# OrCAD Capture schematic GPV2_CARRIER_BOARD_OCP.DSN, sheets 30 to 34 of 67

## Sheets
30 035 M.2_G: size C
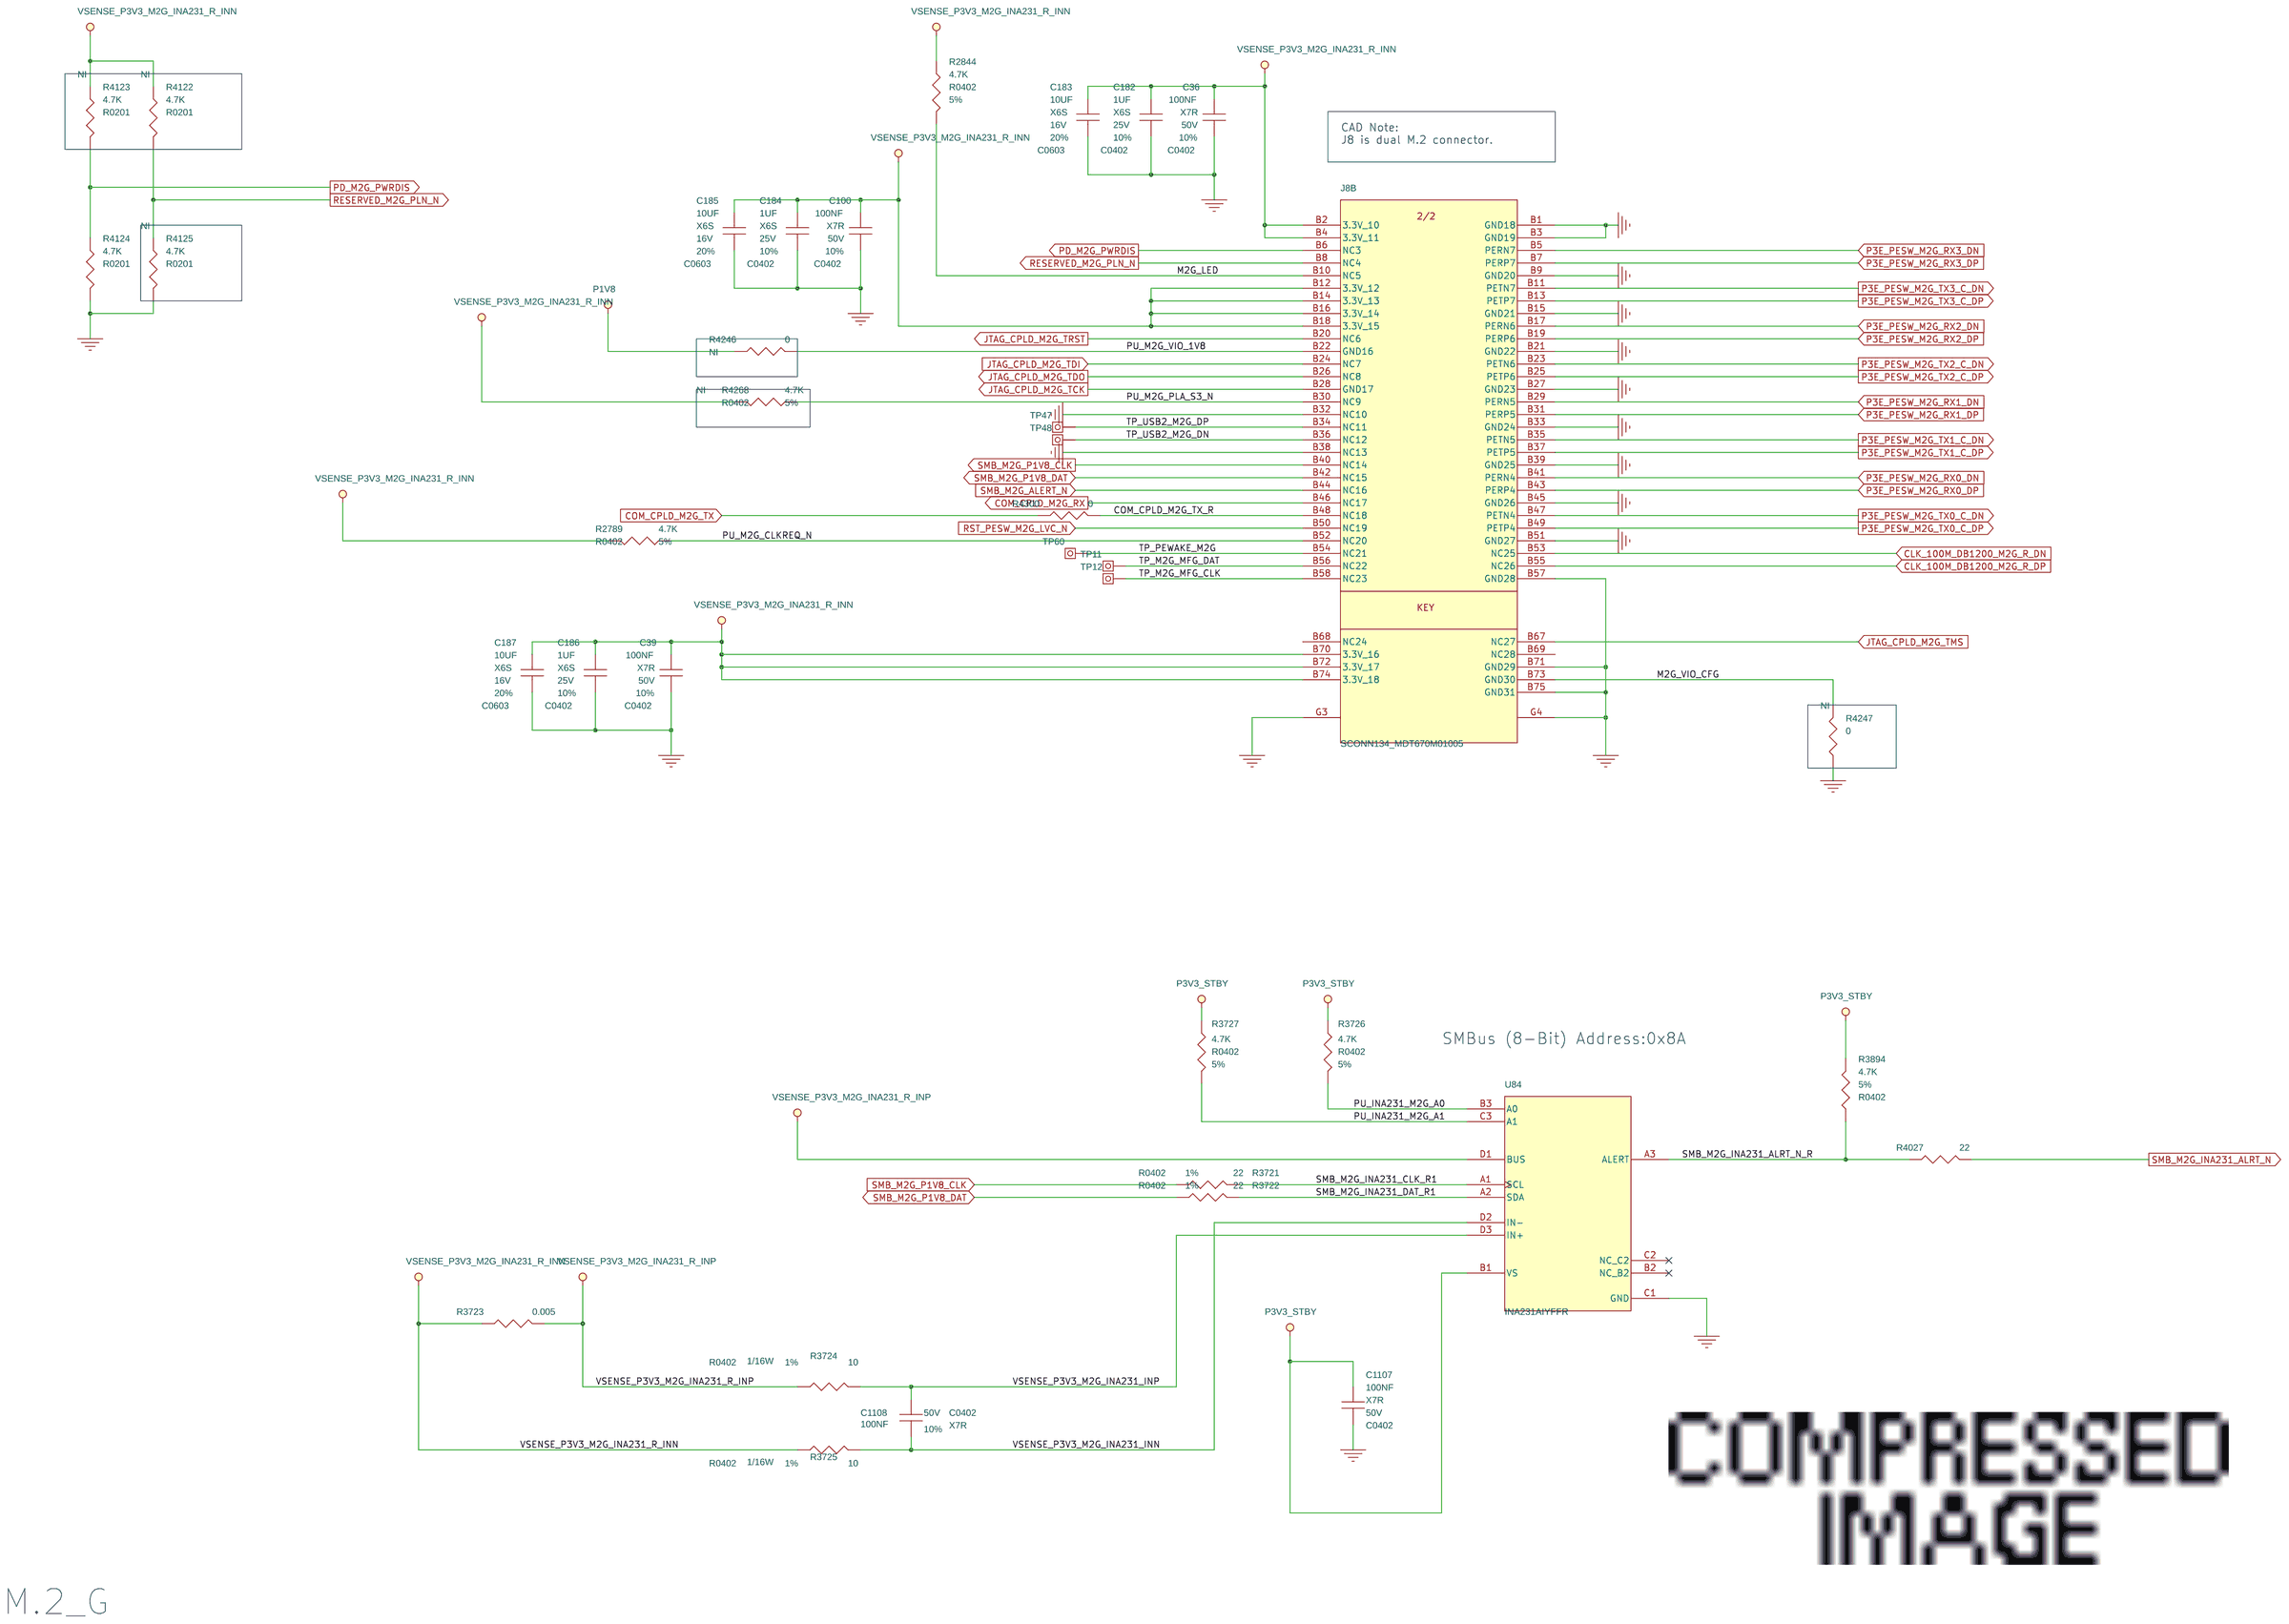
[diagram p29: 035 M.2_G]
31 036 M.2_H: size C
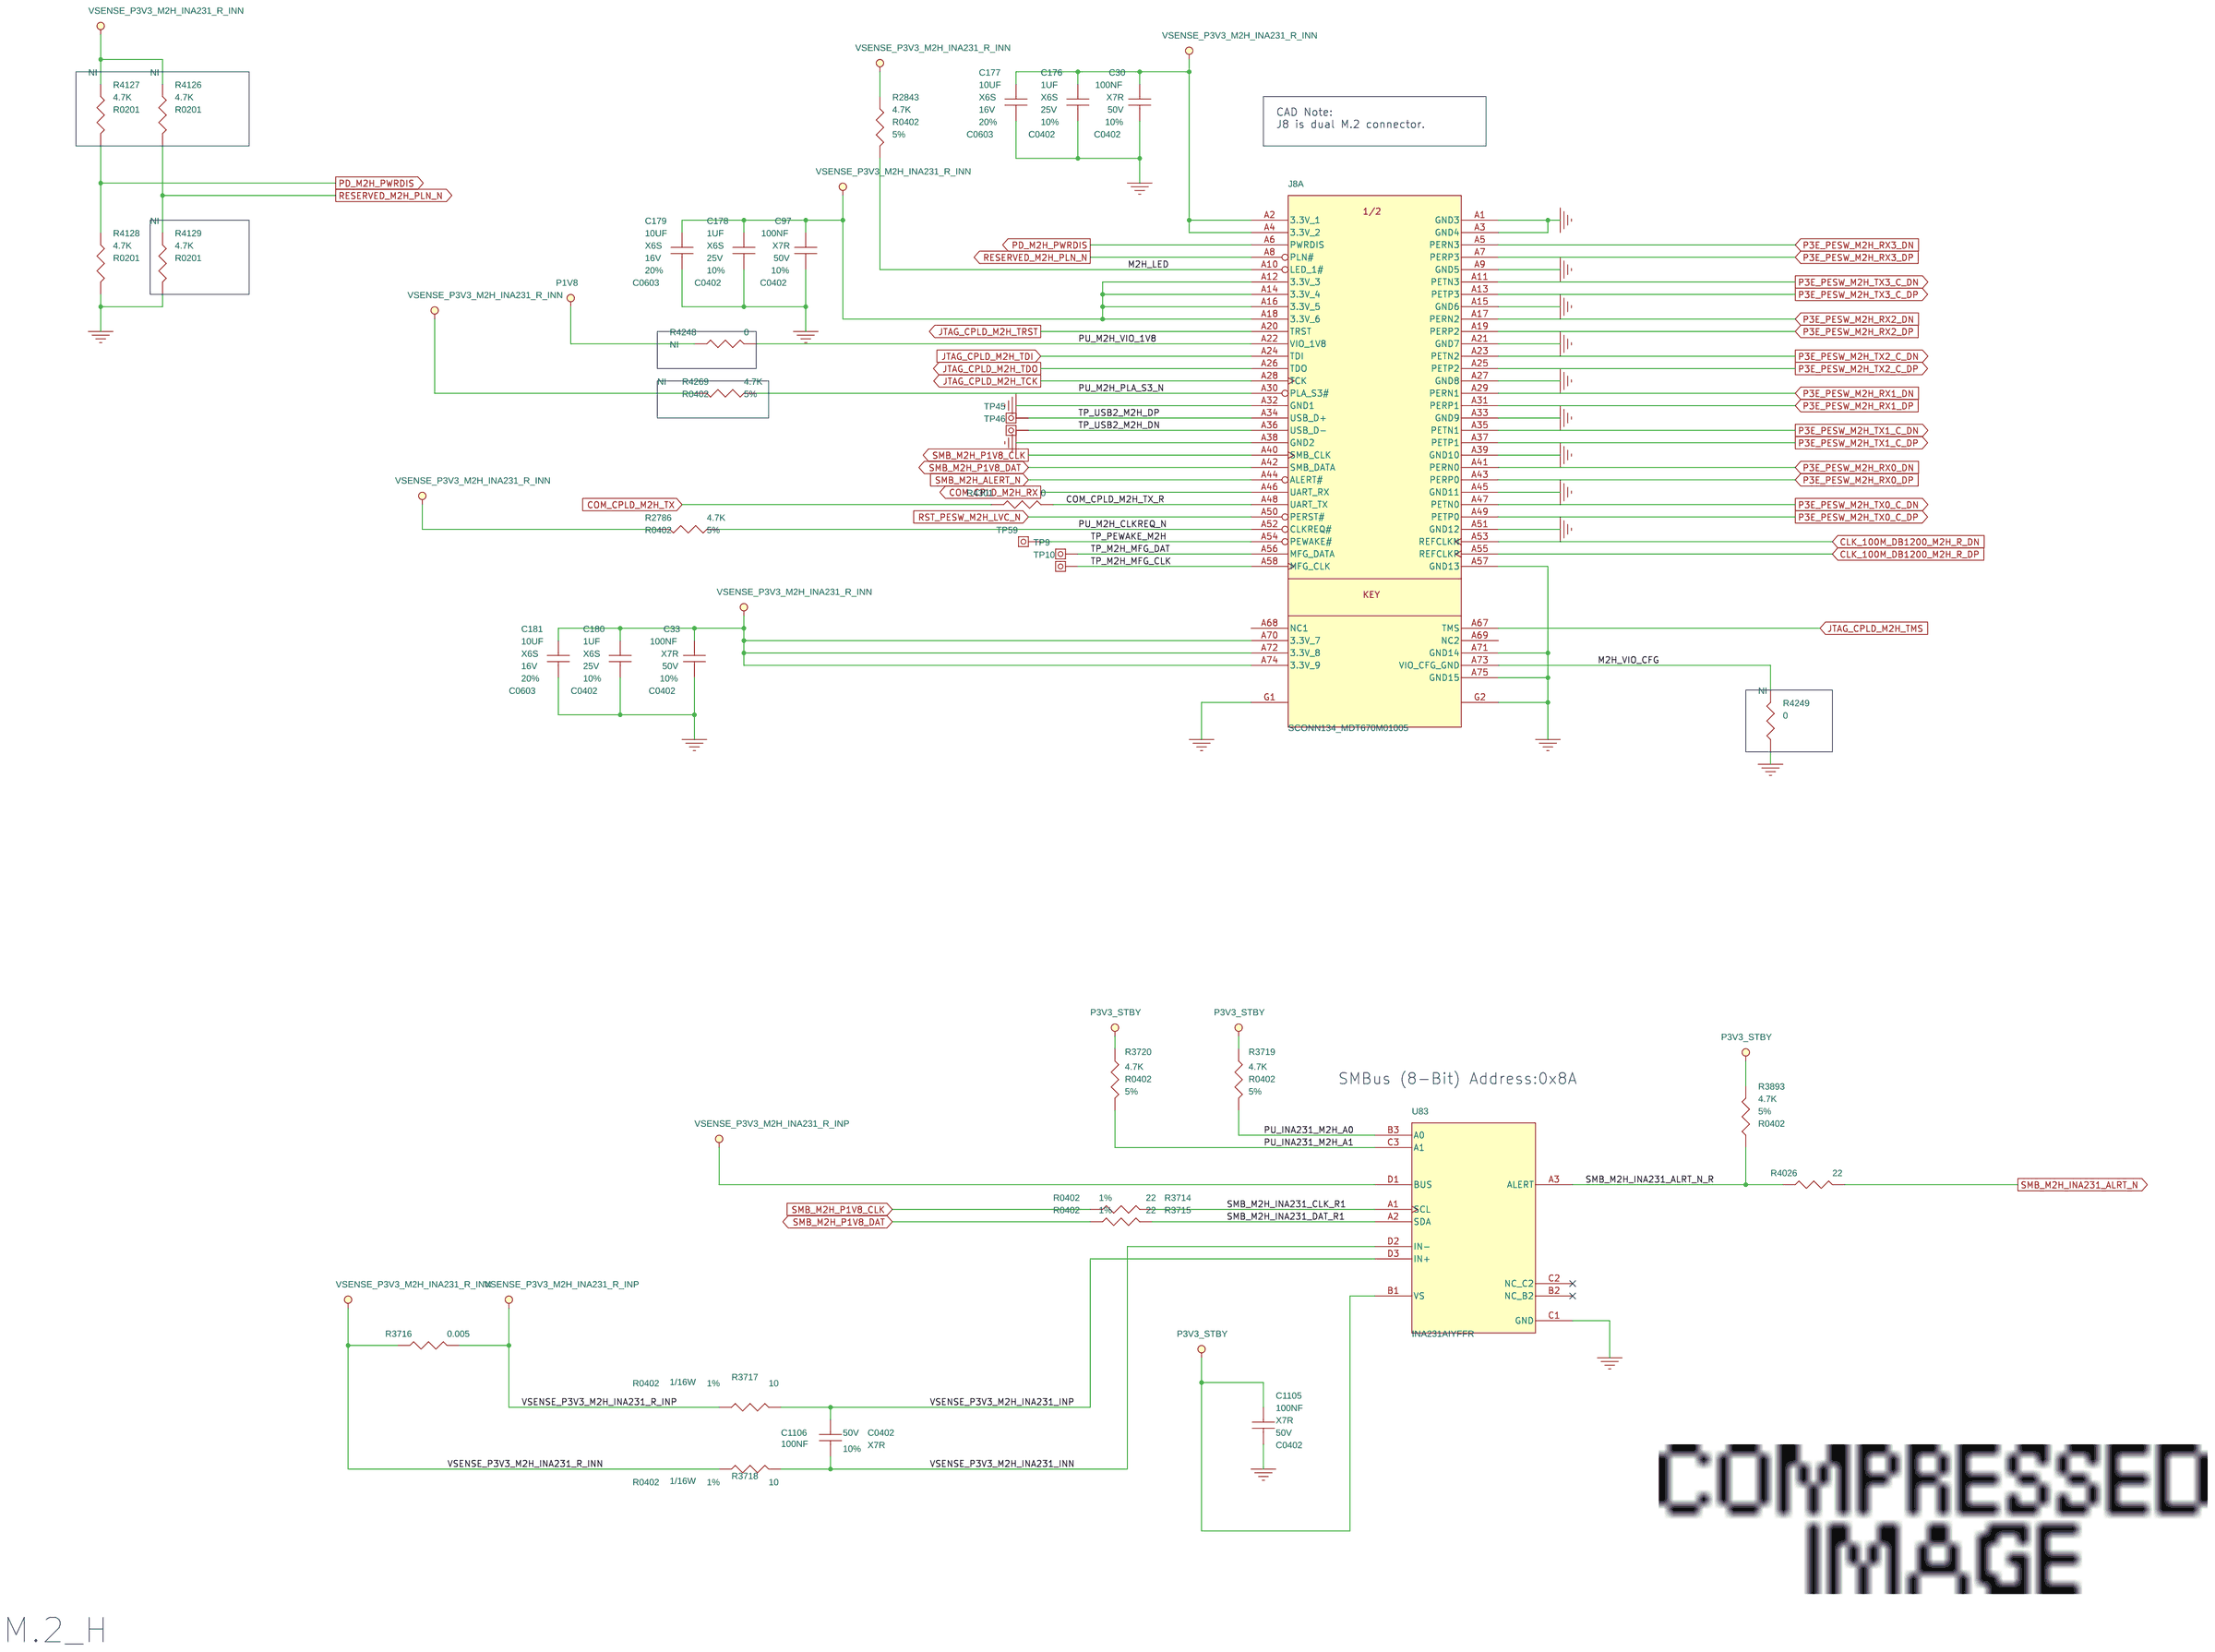
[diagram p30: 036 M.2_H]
32 037 M.2_I: size C
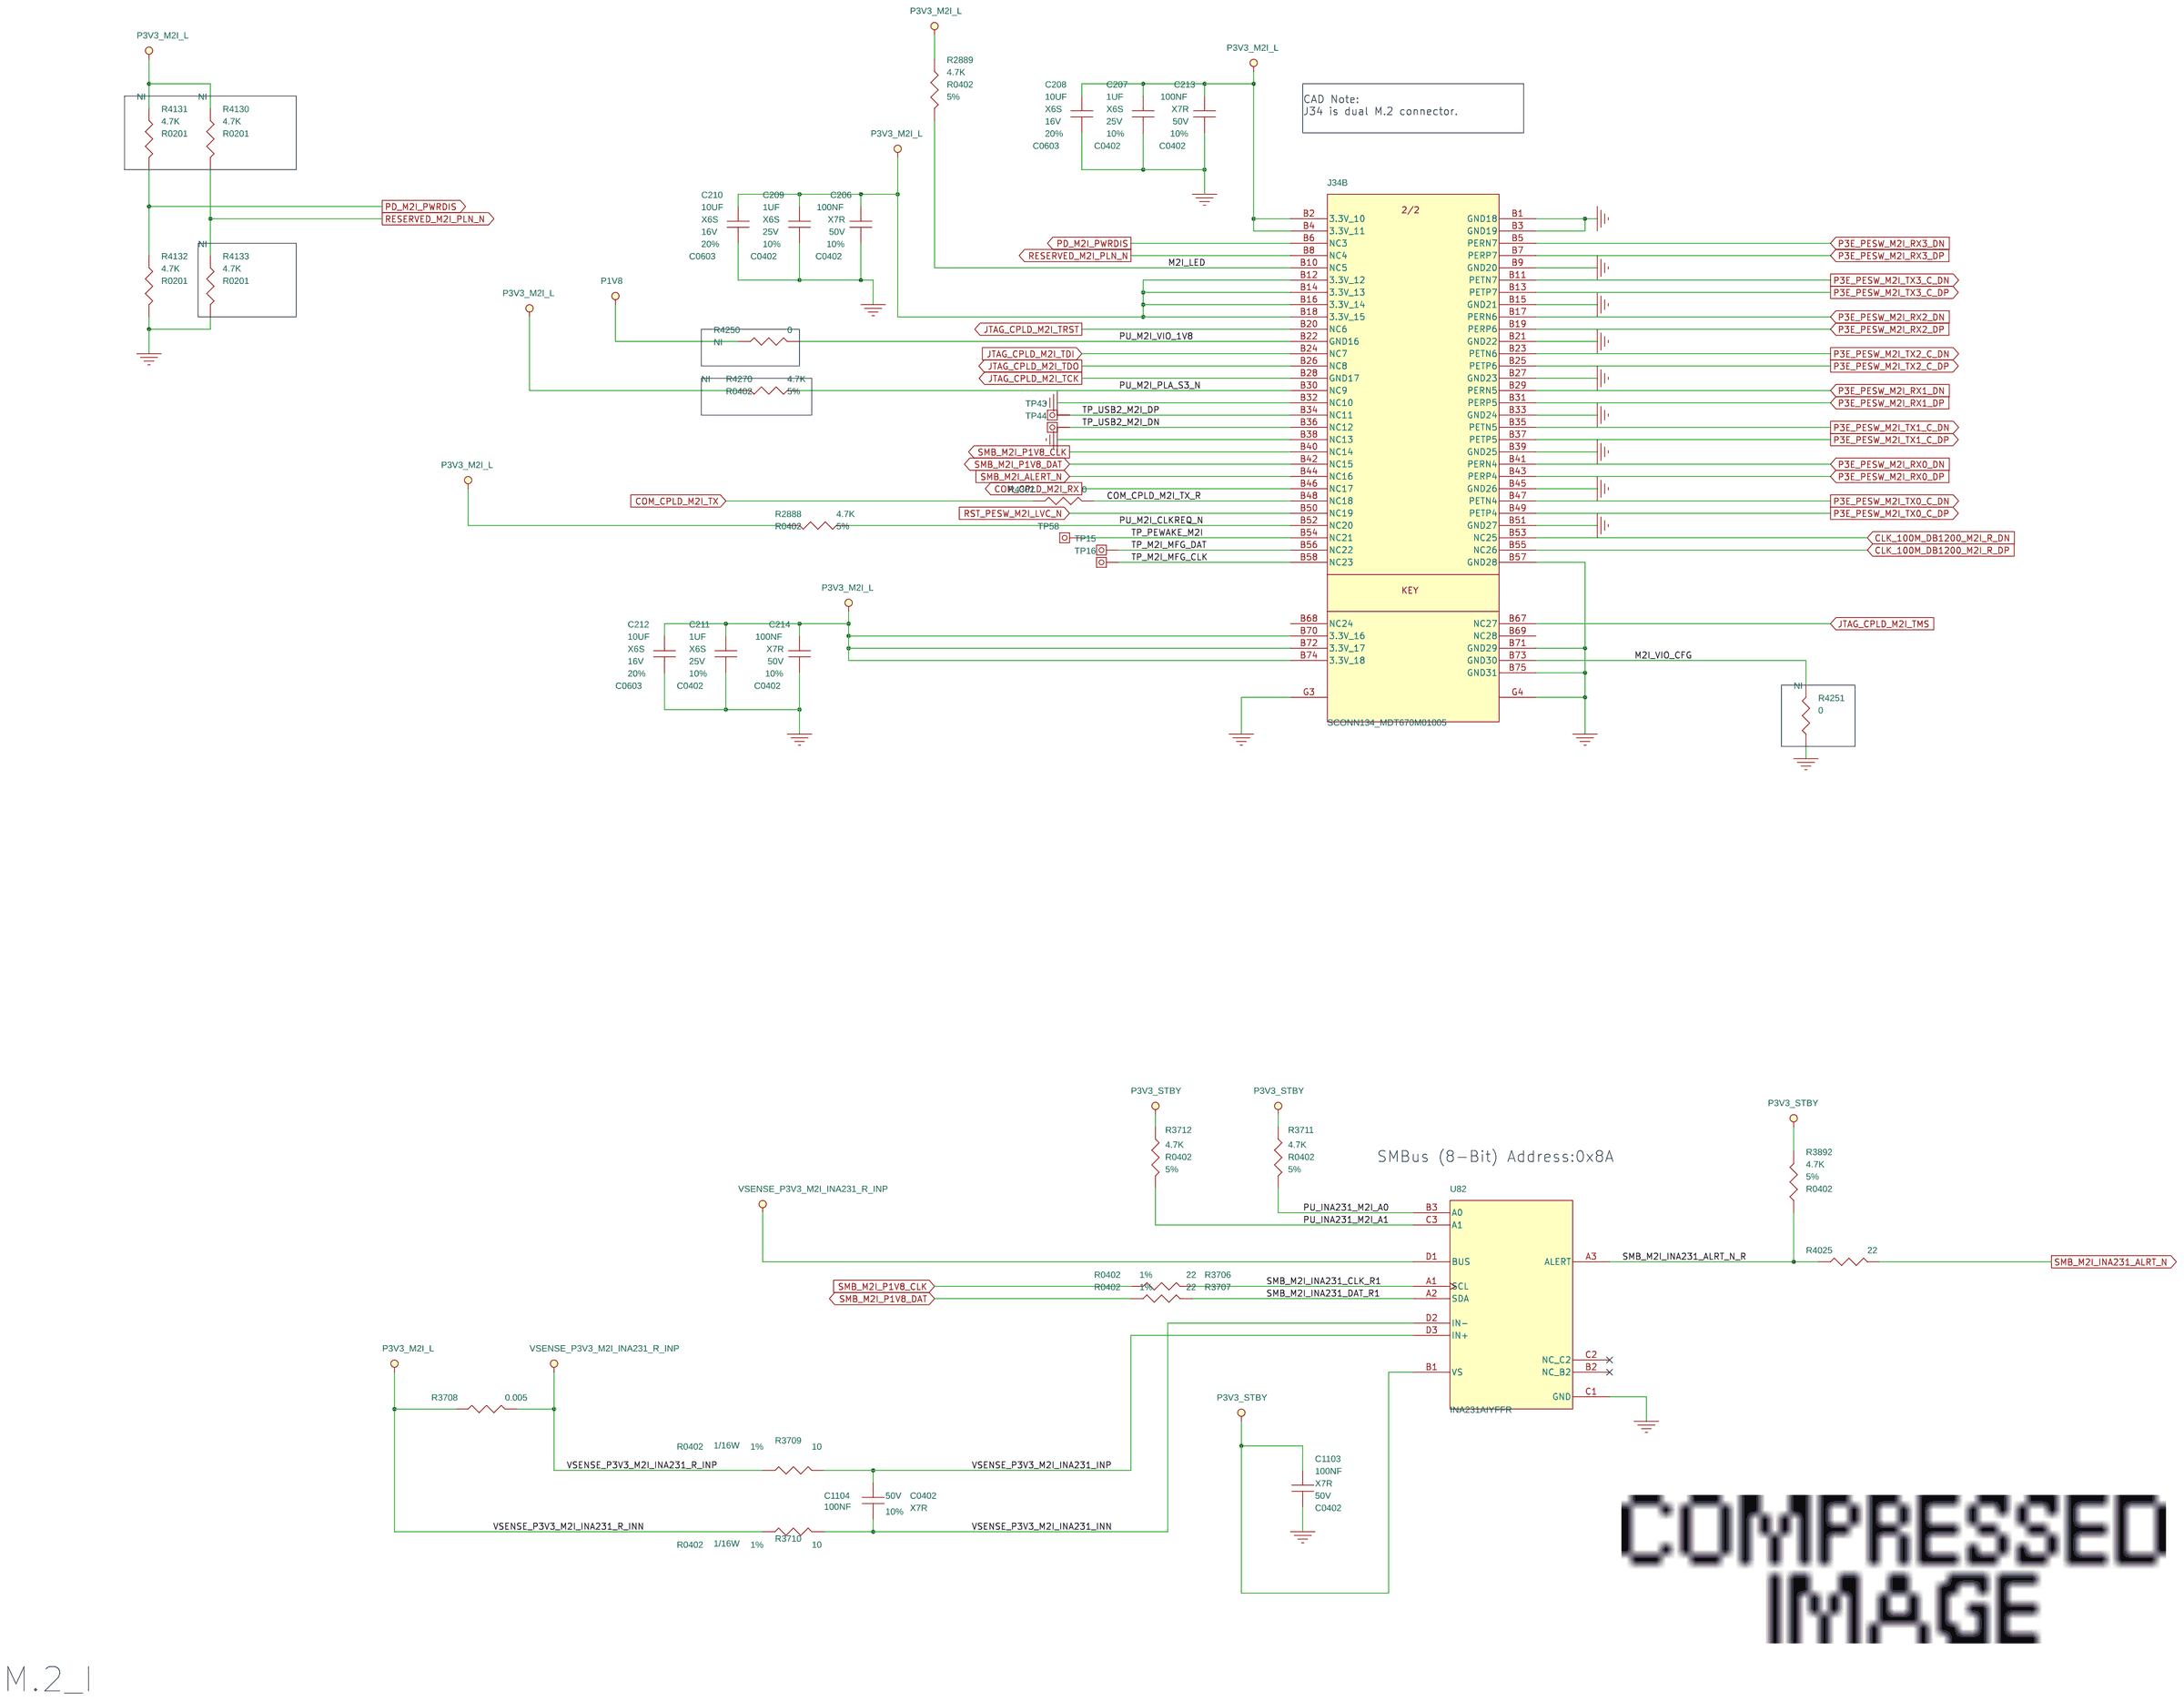
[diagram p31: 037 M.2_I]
33 038 M.2_J: size C
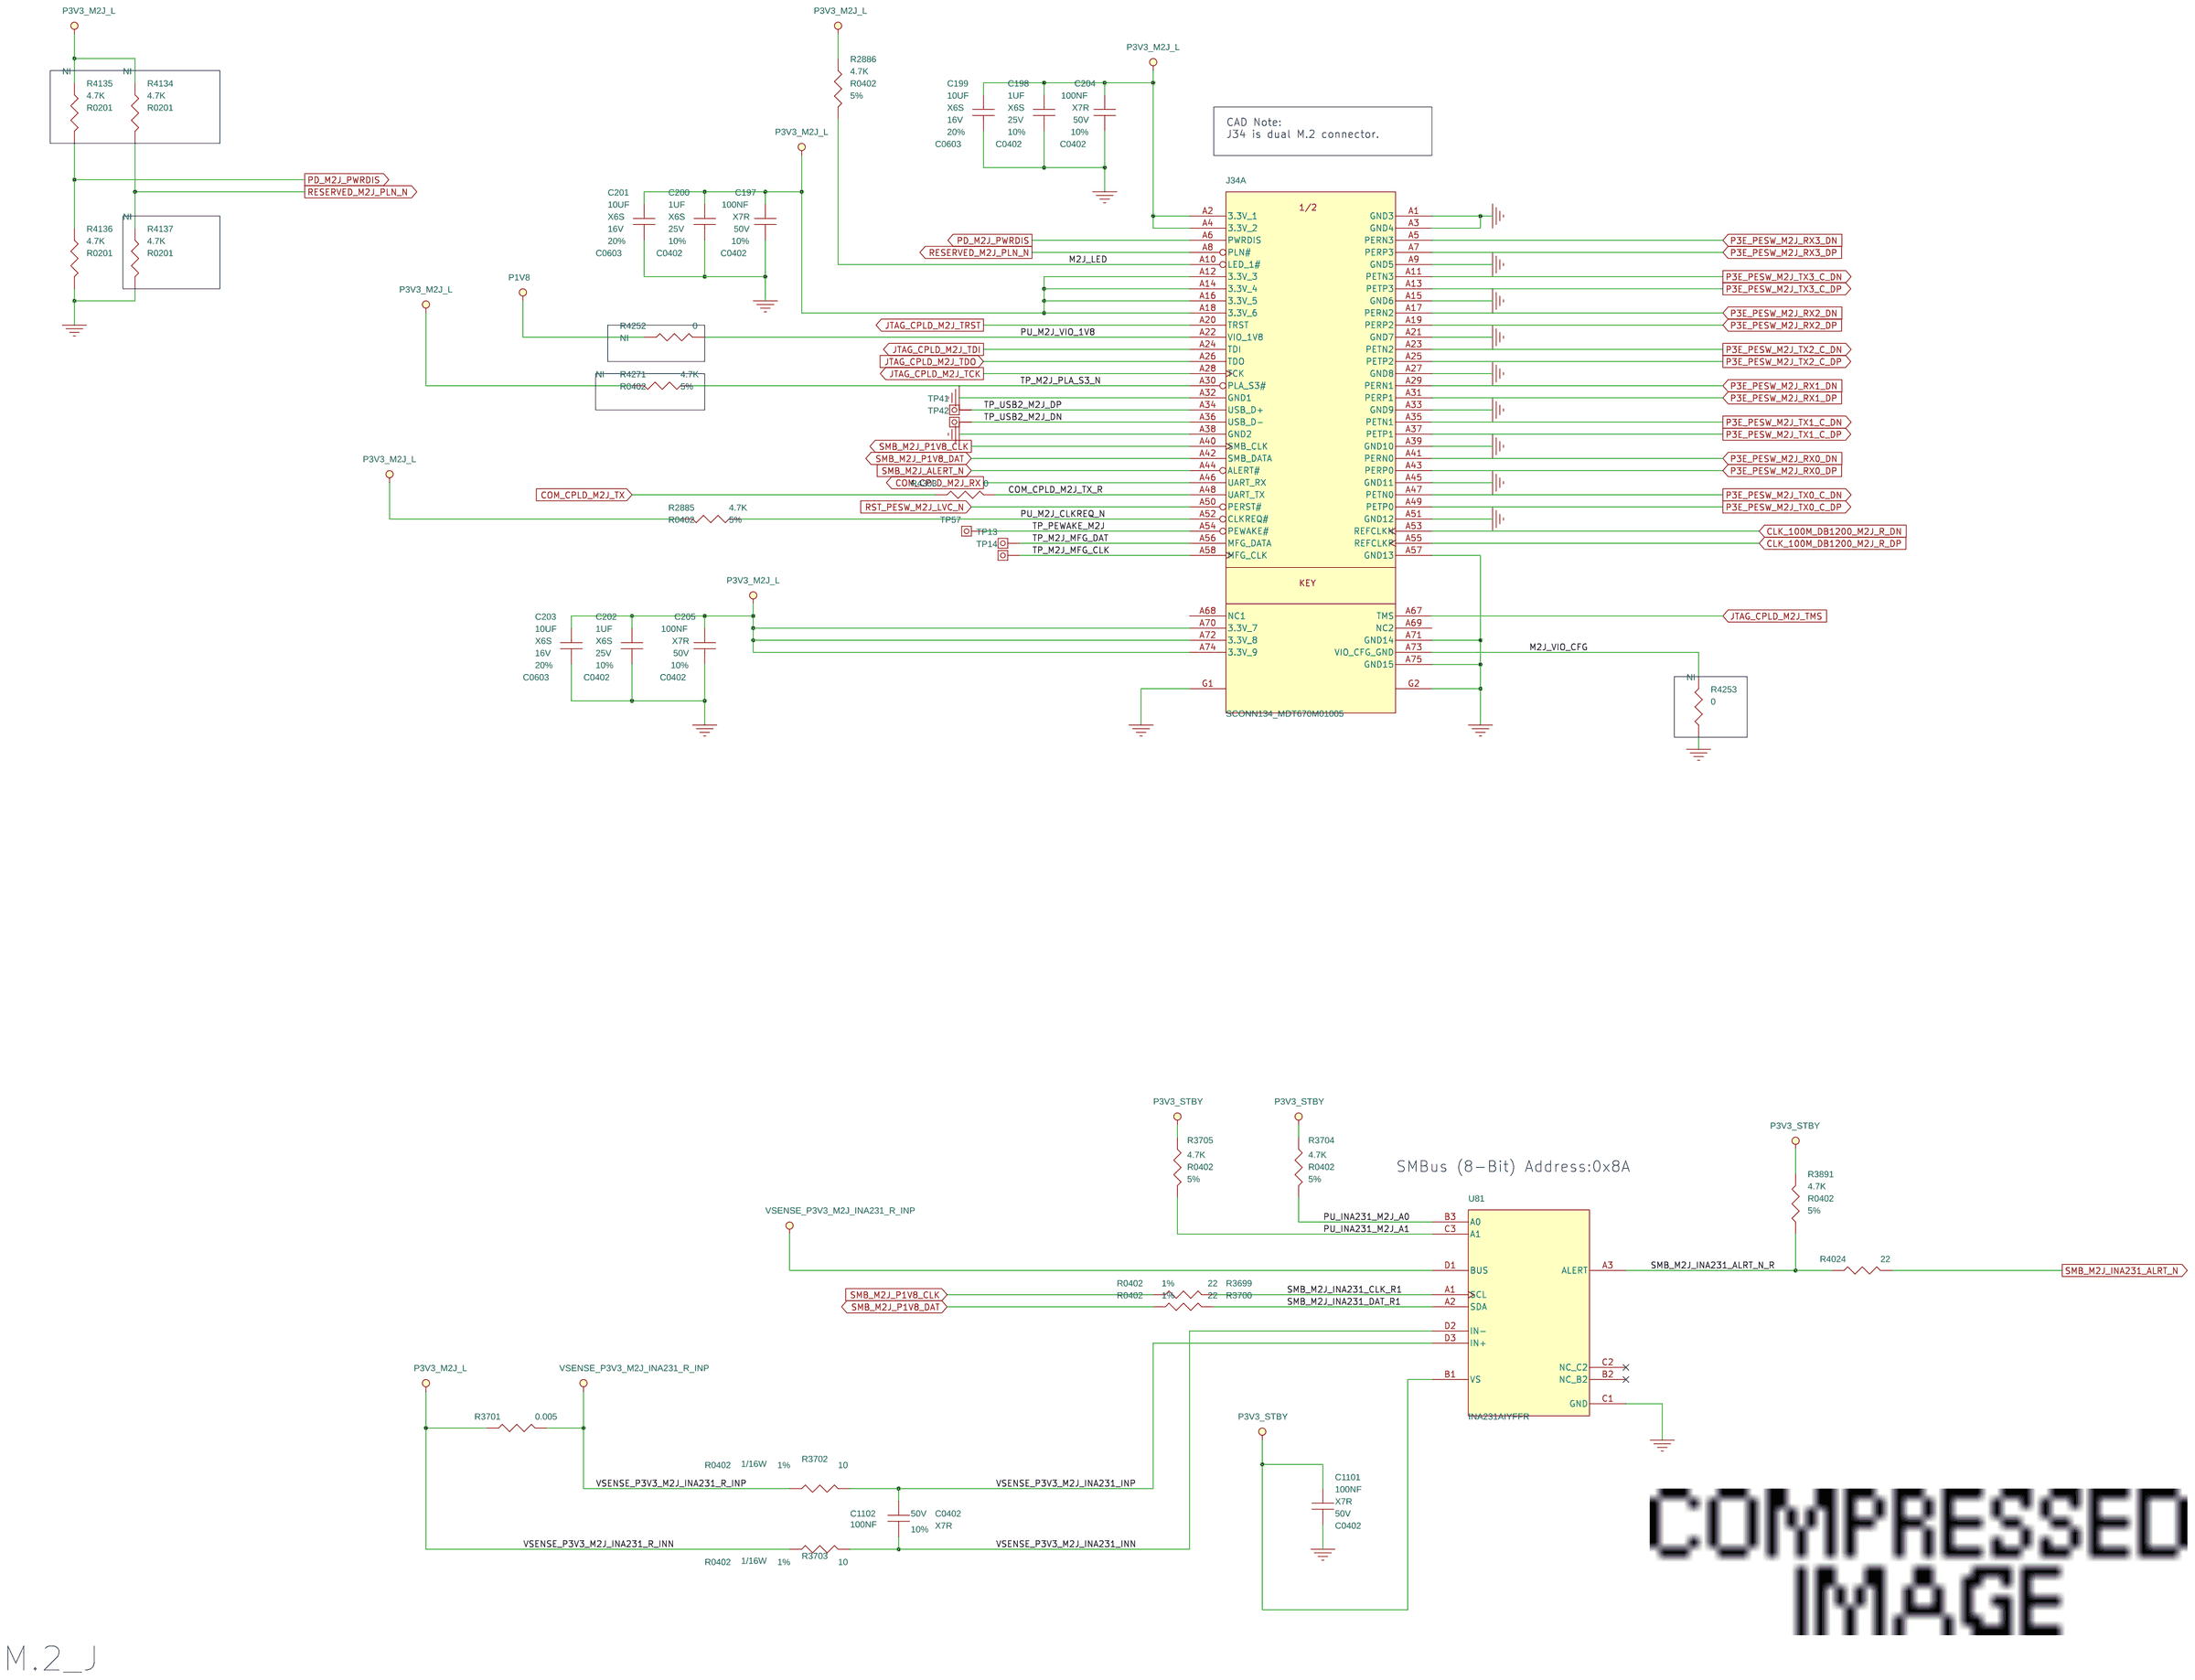
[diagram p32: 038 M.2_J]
34 039 M.2_K: size C
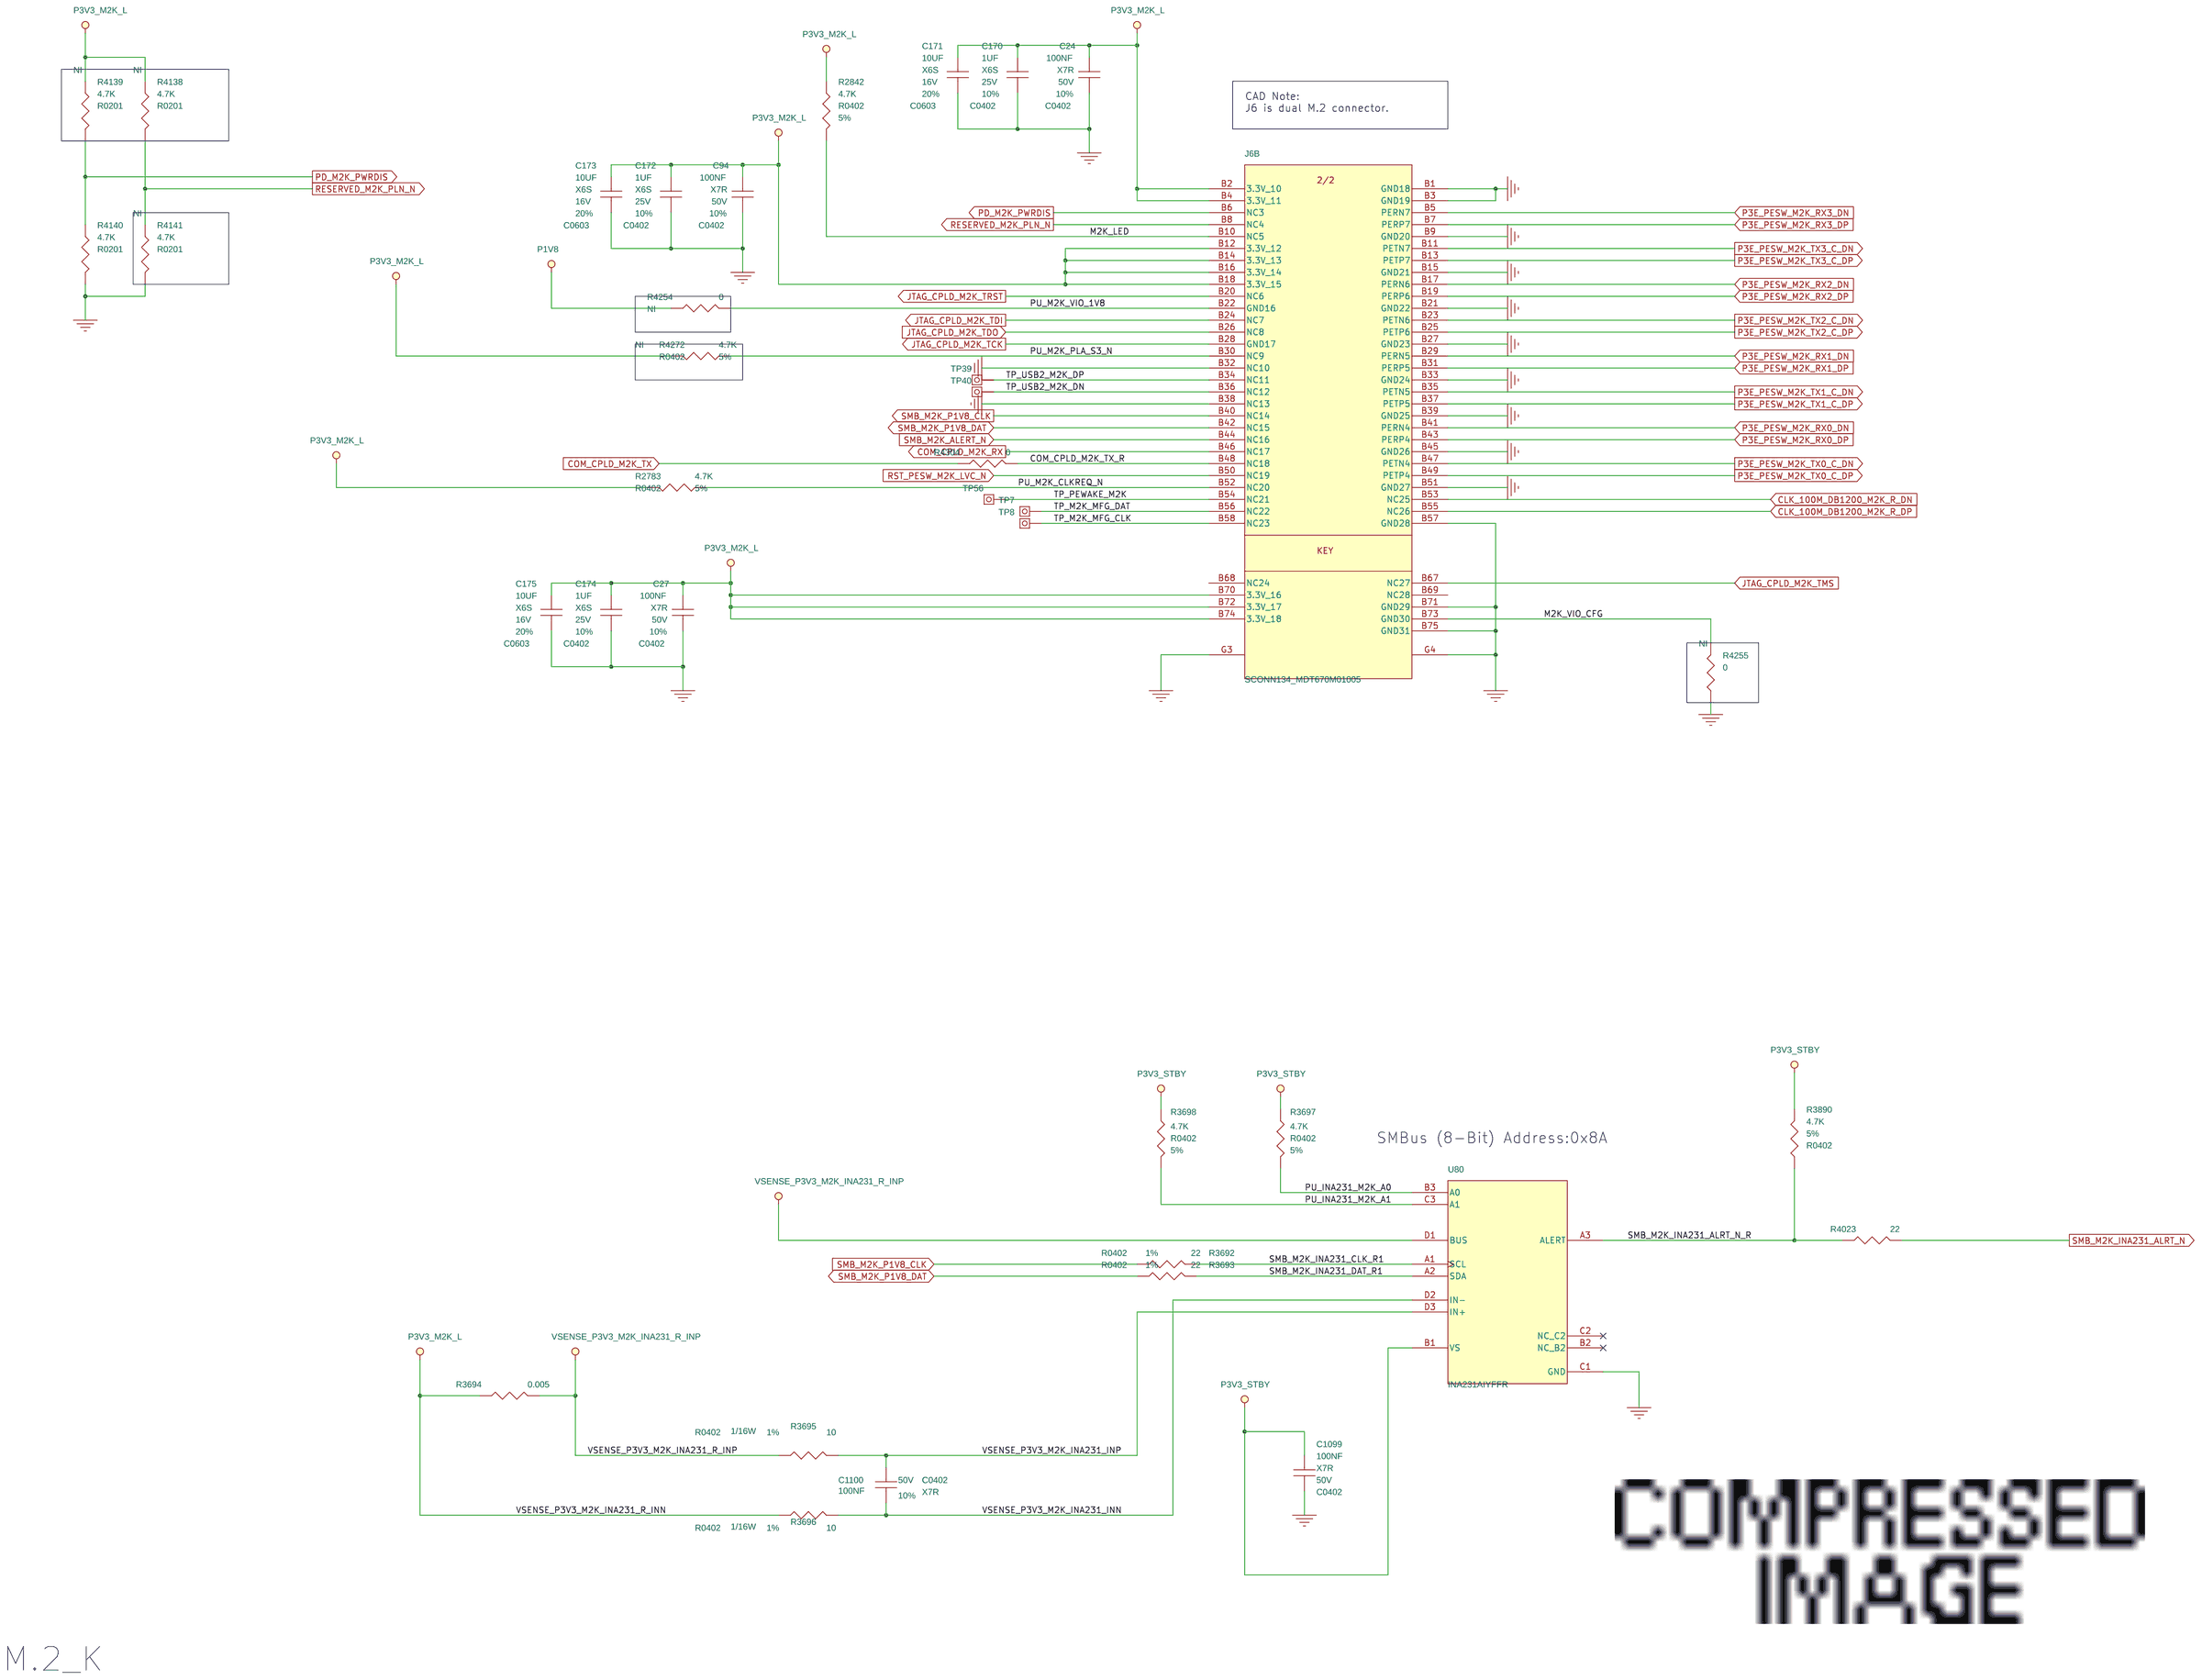
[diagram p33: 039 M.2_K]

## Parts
sheet 035 M.2_G
C36  100NF  [C0402]
C39  100NF  [C0402]
C100  100NF  [C0402]
C182  1UF  [C0402]
C183  10UF  [C0603]
C184  1UF  [C0402]
C185  10UF  [C0603]
C186  1UF  [C0402]
C187  10UF  [C0603]
C1107  100NF  [C0402]
C1108  100NF  [C0402]
J8  SCONN134_MDT670M01005  [CON_F134S2H4D4S_P0-5W7-55_LUVXA]  (sections A,B)
R2789  4.7K  [R0402]
R2844  4.7K  [R0402]
R3721  22  [R0402]
R3722  22  [R0402]
R3723  0.005  [R1206XK]
R3724  10  [R0402]
R3725  10  [R0402]
R3726  4.7K  [R0402]
R3727  4.7K  [R0402]
R3894  4.7K  [R0402]
R4027  22  [R0402]
R4122  4.7K  [R0201]
R4123  4.7K  [R0201]
R4124  4.7K  [R0201]
R4125  4.7K  [R0201]
R4246  0  [R0402]
R4247  0  [R0402]
R4268  4.7K  [R0402]
R4300  0  [R0402]
TP11  TP  [TP26D10]
TP12  TP  [TP26D10]
TP47  TP  [TP26D10]
TP48  TP  [TP26D10]
TP60  TP  [TP26D10]
U84  INA231AIYFFR  [BGA12_0-4_1-388X1-6445]
sheet 036 M.2_H
C30  100NF  [C0402]
C33  100NF  [C0402]
C97  100NF  [C0402]
C176  1UF  [C0402]
C177  10UF  [C0603]
C178  1UF  [C0402]
C179  10UF  [C0603]
C180  1UF  [C0402]
C181  10UF  [C0603]
C1105  100NF  [C0402]
C1106  100NF  [C0402]
R2786  4.7K  [R0402]
R2843  4.7K  [R0402]
R3714  22  [R0402]
R3715  22  [R0402]
R3716  0.005  [R1206XK]
R3717  10  [R0402]
R3718  10  [R0402]
R3719  4.7K  [R0402]
R3720  4.7K  [R0402]
R3893  4.7K  [R0402]
R4026  22  [R0402]
R4126  4.7K  [R0201]
R4127  4.7K  [R0201]
R4128  4.7K  [R0201]
R4129  4.7K  [R0201]
R4248  0  [R0402]
R4249  0  [R0402]
R4269  4.7K  [R0402]
R4301  0  [R0402]
TP9  TP  [TP26D10]
TP10  TP  [TP26D10]
TP45  TP  [TP26D10]
TP46  TP  [TP26D10]
TP59  TP  [TP26D10]
U83  INA231AIYFFR  [BGA12_0-4_1-388X1-6445]
sheet 037 M.2_I
C206  100NF  [C0402]
C207  1UF  [C0402]
C208  10UF  [C0603]
C209  1UF  [C0402]
C210  10UF  [C0603]
C211  1UF  [C0402]
C212  10UF  [C0603]
C213  100NF  [C0402]
C214  100NF  [C0402]
C1103  100NF  [C0402]
C1104  100NF  [C0402]
R2888  4.7K  [R0402]
R2889  4.7K  [R0402]
R3706  22  [R0402]
R3707  22  [R0402]
R3708  0.005  [R1206XK]
R3709  10  [R0402]
R3710  10  [R0402]
R3711  4.7K  [R0402]
R3712  4.7K  [R0402]
R3892  4.7K  [R0402]
R4025  22  [R0402]
R4130  4.7K  [R0201]
R4131  4.7K  [R0201]
R4132  4.7K  [R0201]
R4133  4.7K  [R0201]
R4250  0  [R0402]
R4251  0  [R0402]
R4270  4.7K  [R0402]
R4302  0  [R0402]
TP15  TP  [TP26D10]
TP16  TP  [TP26D10]
TP43  TP  [TP26D10]
TP44  TP  [TP26D10]
TP58  TP  [TP26D10]
U82  INA231AIYFFR  [BGA12_0-4_1-388X1-6445]
sheet 038 M.2_J
C197  100NF  [C0402]
C198  1UF  [C0402]
C199  10UF  [C0603]
C200  1UF  [C0402]
C201  10UF  [C0603]
C202  1UF  [C0402]
C203  10UF  [C0603]
C204  100NF  [C0402]
C205  100NF  [C0402]
C1101  100NF  [C0402]
C1102  100NF  [C0402]
J34  SCONN134_MDT670M01005  [CON_F134S2H4D4S_P0-5W7-55_LUVXA]  (sections A,B)
R2885  4.7K  [R0402]
R2886  4.7K  [R0402]
R3699  22  [R0402]
R3700  22  [R0402]
R3701  0.005  [R1206XK]
R3702  10  [R0402]
R3703  10  [R0402]
R3704  4.7K  [R0402]
R3705  4.7K  [R0402]
R3891  4.7K  [R0402]
R4024  22  [R0402]
R4134  4.7K  [R0201]
R4135  4.7K  [R0201]
R4136  4.7K  [R0201]
R4137  4.7K  [R0201]
R4252  0  [R0402]
R4253  0  [R0402]
R4271  4.7K  [R0402]
R4303  0  [R0402]
TP13  TP  [TP26D10]
TP14  TP  [TP26D10]
TP41  TP  [TP26D10]
TP42  TP  [TP26D10]
TP57  TP  [TP26D10]
U81  INA231AIYFFR  [BGA12_0-4_1-388X1-6445]
sheet 039 M.2_K
C24  100NF  [C0402]
C27  100NF  [C0402]
C94  100NF  [C0402]
C170  1UF  [C0402]
C171  10UF  [C0603]
C172  1UF  [C0402]
C173  10UF  [C0603]
C174  1UF  [C0402]
C175  10UF  [C0603]
C1099  100NF  [C0402]
C1100  100NF  [C0402]
J6  SCONN134_MDT670M01005  [CON_F134S2H4D4S_P0-5W7-55_LUVXA]  (sections A,B)
R2783  4.7K  [R0402]
R2842  4.7K  [R0402]
R3692  22  [R0402]
R3693  22  [R0402]
R3694  0.005  [R1206XK]
R3695  10  [R0402]
R3696  10  [R0402]
R3697  4.7K  [R0402]
R3698  4.7K  [R0402]
R3890  4.7K  [R0402]
R4023  22  [R0402]
R4138  4.7K  [R0201]
R4139  4.7K  [R0201]
R4140  4.7K  [R0201]
R4141  4.7K  [R0201]
R4254  0  [R0402]
R4255  0  [R0402]
R4272  4.7K  [R0402]
R4304  0  [R0402]
TP7  TP  [TP26D10]
TP8  TP  [TP26D10]
TP39  TP  [TP26D10]
TP40  TP  [TP26D10]
TP56  TP  [TP26D10]
U80  INA231AIYFFR  [BGA12_0-4_1-388X1-6445]

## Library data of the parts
C24 C27 C30 C33 C36 C39 C94 C97 C100 C197 C204-C206 C213 C214 = CAP_NP: CAP CHIP 100NF 50V(+-10%,X7R,0402); CLASS: DISCRETE; MATERIAL: X7R; Manuf_PN: CC0402KRX7R9BB104; Manuf_name: YAGEO CORPORATION; Manufacturer: MUR; Manuftr: YGO; Part_Type: *LF_C0402; TOLERANCE: 10%; VOLTAGE: 50V
C170 C172 C174 C176 C178 C180 C182 C184 C186 C198 C200 C202 C207 C209 C211 = CAP_NP: CAP CHIP 1UF 25V(+-10%,X6S,0402); CLASS: DISCRETE; MATERIAL: X6S; Manuf_PN: GRM155C81E105K; Manuf_name: MURATA ERIE N.A. INC TAIWAN BRANCH Okayama Murata Mfg.Co..Ltd.Wakura Murata Mfg.; Manuftr: MUR; Part_Type: *LF_C0402; TOLERANCE: 10%; VOLTAGE: 25V
C171 C173 C175 C177 C179 C181 C183 C185 C187 C199 C201 C203 C208 C210 C212 = CAP_NP: CAP CHIP 10U 16V(+-20%,X6S,0603); CLASS: DISCRETE; MATERIAL: X6S; Manuf_PN: GRM188C81C106M; Manuf_name: MURATA ERIE N.A. INC TAIWAN BRANCH Okayama Murata Mfg.Co..Ltd. Wakura Murata Mfg; Manuftr: MUR; Part_Type: *LF_C0603; TOLERANCE: 20%; VOLTAGE: 16V
C1099 C1101 C1103 C1105 C1107 = CAP_NP: CAP CHIP 100NF 50V(+-10%,X7R,0402); CLASS: DISCRETE; MATERIAL: X7R; Manuf_PN: CC0402KRX7R9BB104; Manuf_name: YAGEO CORPORATION; Manufacturer: AVX; Manuftr: YGO; Part_Type: *LF_C0402; TOLERANCE: 10%; VOLTAGE: 50V
C1100 C1102 C1104 C1106 C1108 = CAP_NP: CAP CHIP 100NF 50V(+-10%,X7R,0402); CLASS: DISCRETE; MATERIAL: X7R; Manuf_PN: CC0402KRX7R9BB104; Manuf_name: YAGEO CORPORATION; Manuftr: YGO; Part_Type: *LF_C0402; TOLERANCE: 10%; VOLTAGE: 50V
J6 J8 J34 = SCONN134_MDT670M01005: CONN SMD HOUSING 150P 2R FR(P0.5,H6.7); CLASS: IO; ESD_CDM: N/A; ESD_HBM: N/A; ESD_MM: N/A; MATERIAL: IO; MSD: NA; Manuf_PN: MDT670M01005; Manuf_name: AMPHENOL EAST ASIA LIMITED (Amphenol-TCS) (Shangh; Manuftr: APL; PIN_LENGTH_LONG_PIN: 20MILS; PIN_LENGTH_SHORT_PIN: 20MILS; Part_Type: *LF_Connector
R2783 R2786 R2789 R2842-R2844 R2885 R2886 R2888 R2889 = R: RES CHIP 4.7K 1/16W +-5% (0402); CLASS: DISCRETE; MATERIAL: CHIP; Manuf_PN: RR0510S-472-JN; Manuf_name: CYNTEC CO.. LTD.; Manufacturer: CYN; Manuftr: CYN; Part_Type: *LF_Resistor; TOLERANCE: 5%; WATTAGE: 1/16W
R3692 R3693 R3699 R3700 R3706 R3707 R3714 R3715 R3721 R3722 = R: RES CHIP 22 1/16W +-1%(0402); BOM: AST2300; CLASS: DISCRETE; MATERIAL: CHIP; Manuf_PN: CR0222R0F002S; Manuf_name: RTECH TECHNOLOGY CO..LTD. (Compostar); Manufacturer: CYN; Manuftr: RHT; Part_Type: *LF_Resistor; TOLERANCE: 1%; WATTAGE: 1/16W
R3694 R3701 R3708 R3716 R3723 = R: RES CHIP  0.005  1W +-1%(1206); CLASS: DISCRETE; ESD_CDM: NA; ESD_HBM: NA; ESD_MM: NA; MATERIAL: CHIP; MSD: NA; Manuf_PN: RLM12FTCMR005; Manuf_name: TA-I TECHNOLOGY CO.,LTD.; Manuftr: TAI; PIN_LENGTH_LONG_PIN: 0 MILS; PIN_LENGTH_SHORT_PIN: 0 MILS; Part_Type: *LF_Resistor; TOLERANCE: 1%; WATTAGE: 1W
R3695 R3696 R3702 R3703 R3709 R3710 R3717 R3718 R3724 R3725 = R: RES CHIP 10 1/16W +-1%(0402); CLASS: DISCRETE; MATERIAL: CHIP; Manuf_PN: RM04FTN10R0; Manuf_name: TA-I TECHNOLOGY CO..LTD.; Manuftr: TAI; Part_Type: *LF_Resistor; TOLERANCE: 1%; WATTAGE: 1/16W
R3697 R3698 R3704 R3705 R3711 R3712 R3719 R3720 R3726 R3727 R3890-R3894 = R: RES CHIP 4.7K 1/16W +-5% (0402); CLASS: DISCRETE; MATERIAL: CHIP; Manuf_PN: RR0510S-472-JN; Manuf_name: CYNTEC CO.. LTD.; Manuftr: CYN; Part_Type: *LF_Resistor; TOLERANCE: 5%; WATTAGE: 1/16W
R4023-R4027 = R: RES CHIP 22 1/16W +-1%(0402); CLASS: DISCRETE; MATERIAL: CHIP; Manuf_PN: CR0222R0F002S; Manuf_name: RTECH TECHNOLOGY CO..LTD. (Compostar); Manuftr: RHT; Part_Type: *LF_Resistor; TOLERANCE: 1%; WATTAGE: 1/16W
R4122 R4123 R4125-R4127 R4129-R4131 R4133-R4135 R4137-R4139 R4141 = R: RES CHIP 4.7K(1/20W,+-5%,0201); CLASS: DISCRETE; MATERIAL: CHIP; Manuf_PN: RR0306S-472-JN; Manuf_name: CYNTEC CO., LTD.; Manuftr: CYN; Not_insert: NI; Part_Type: *LF_Resistor; TOLERANCE: 5%; WATTAGE: 1/20W
R4124 R4128 R4132 R4136 R4140 = R: RES CHIP 4.7K(1/20W,+-5%,0201); CLASS: DISCRETE; MATERIAL: CHIP; Manuf_PN: RR0306S-472-JN; Manuf_name: CYNTEC CO., LTD.; Manuftr: CYN; Part_Type: *LF_Resistor; TOLERANCE: 5%; WATTAGE: 1/20W
R4246-R4255 = R: RESISTOR CHIP 0 1/16W +-5%(0402); CLASS: DISCRETE; MATERIAL: CHIP; Manuf_PN: RR0510X-000-XN; Manuf_name: CYNTEC CO.. LTD.; Manuftr: CYN; Not_insert: NI; Part_Type: *LF_Resistor; TOLERANCE: 5%; WATTAGE: 1/16W
R4268-R4272 = R: RES CHIP 4.7K 1/16W +-5% (0402); CLASS: DISCRETE; MATERIAL: CHIP; Manuf_PN: RR0510S-472-JN; Manuf_name: CYNTEC CO.. LTD.; Manufacturer: CYN; Manuftr: CYN; Not_insert: NI; Part_Type: *LF_Resistor; TOLERANCE: 5%; WATTAGE: 1/16W
R4300-R4304 = R: RESISTOR CHIP 0 1/16W +-5%(0402); CLASS: DISCRETE; MATERIAL: CHIP; Manuf_PN: RR0510X-000-XN; Manuf_name: CYNTEC CO.. LTD.; Manuftr: CYN; Part_Type: *LF_Resistor; TOLERANCE: 5%; WATTAGE: 1/16W
TP7-TP16 TP39-TP48 TP56-TP60 = TP: TEST POINT (TP26D10) DIP(DRILL10MILS); ALT_SYMBOLS: TOP:TP26D10;BOTTOM:TP30D10; CLASS: IO; Cost: CPU; DIP_SMD: DIP; MATERIAL: MISC; Not_insert: NI; Part_Type: Misc; SUBSYS: CPU_CONN
U80-U84 = INA231AIYFFR: IC OTHER (12P) INA231AIYFFR (DSBGA); CLASS: IC; ESD_CDM: 1000; ESD_HBM: 2500; ESD_MM: 150; MATERIAL: IC; MSD: Level-1; Manuf_name: TEXAS INSTRUMENTS SUPPLY CO.,; Manuftr: TIC; PIN_LENGTH_LONG_PIN: 0 MILS; PIN_LENGTH_SHORT_PIN: 0 MILS; Part_Type: *LF_Chipset

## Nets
GND: C24.2 C27.2 C30.2 C33.2 C36.2 C39.2 C94.2 C97.2 C100.2 C170.2 C171.2 C172.2 C173.2 C174.2 C175.2 C176.2 C177.2 C178.2 C179.2 C180.2 C181.2 C182.2 C183.2 C184.2 C185.2 C186.2 C187.2 C197.2 C198.2 C199.2 C200.2 C201.2 C202.2 C203.2 C204.2 C205.2 C206.2 C207.2 C208.2 C209.2 C210.2 C211.2 C212.2 C213.2 C214.2 C1099.2 C1101.2 C1103.2 C1105.2 C1107.2 J6.B1(GND18) J6.B3(GND19) J6.B9(GND20) J6.B15(GND21) J6.B21(GND22) J6.B27(GND23) J6.B32(NC10) J6.B33(GND24) J6.B38(NC13) J6.B39(GND25) J6.B45(GND26) J6.B51(GND27) J6.B57(GND28) J6.B71(GND29) J6.B75(GND31) J6.G3 J6.G4 J8.A1(GND3) J8.A3(GND4) J8.A9(GND5) J8.A15(GND6) J8.A21(GND7) J8.A27(GND8) J8.A32(GND1) J8.A33(GND9) J8.A38(GND2) J8.A39(GND10) J8.A45(GND11) J8.A51(GND12) J8.A57(GND13) J8.A71(GND14) J8.A75(GND15) J8.B1(GND18) J8.B3(GND19) J8.B9(GND20) J8.B15(GND21) J8.B21(GND22) J8.B27(GND23) J8.B32(NC10) J8.B33(GND24) J8.B38(NC13) J8.B39(GND25) J8.B45(GND26) J8.B51(GND27) J8.B57(GND28) J8.B71(GND29) J8.B75(GND31) J8.G1 J8.G2 J8.G3 J8.G4 J34.A1(GND3) J34.A3(GND4) J34.A9(GND5) J34.A15(GND6) J34.A21(GND7) J34.A27(GND8) J34.A32(GND1) J34.A33(GND9) J34.A38(GND2) J34.A39(GND10) J34.A45(GND11) J34.A51(GND12) J34.A57(GND13) J34.A71(GND14) J34.A75(GND15) J34.B1(GND18) J34.B3(GND19) J34.B9(GND20) J34.B15(GND21) J34.B21(GND22) J34.B27(GND23) J34.B32(NC10) J34.B33(GND24) J34.B38(NC13) J34.B39(GND25) J34.B45(GND26) J34.B51(GND27) J34.B57(GND28) J34.B71(GND29) J34.B75(GND31) J34.G1 J34.G2 J34.G3 J34.G4 R4124.2 R4125.2 R4128.2 R4129.2 R4132.2 R4133.2 R4136.2 R4137.2 R4140.2 R4141.2 R4247.1 R4249.1 R4251.1 R4253.1 R4255.1 U80.C1(GND) U81.C1(GND) U82.C1(GND) U83.C1(GND) U84.C1(GND) ; also on sheet 12 13 17 18 19 20 21 22 23 24 25 26 27 28 29 35 36 37 38 39 40 41 42 43 44 45 46 47 48 49 50 52 53 54 55 56 57 58 61 62 63 64 65 66 67
P1V8: R4246.1 R4248.1 R4250.1 R4252.1 R4254.1 ; also on sheet 17 18 19 22 23 24 25 26 27 28 29 35 36 37 44 49 50 53 58 62 65 67
P3V3_M2G: R3723.2 R3724.1 U84.D1(BUS) ; also on sheet 40
P3V3_M2G_L: C36.1 C39.1 C100.1 C182.1 C183.1 C184.1 C185.1 C186.1 C187.1 J8.B2(3.3V_10) J8.B4(3.3V_11) J8.B12(3.3V_12) J8.B14(3.3V_13) J8.B16(3.3V_14) J8.B18(3.3V_15) J8.B70(3.3V_16) J8.B72(3.3V_17) J8.B74(3.3V_18) R2789.2 R2844.1 R3723.1 R3725.1 R4122.1 R4123.1 R4268.2
P3V3_M2H: R3716.2 R3717.1 U83.D1(BUS) ; also on sheet 40
P3V3_M2H_L: C30.1 C33.1 C97.1 C176.1 C177.1 C178.1 C179.1 C180.1 C181.1 J8.A2(3.3V_1) J8.A4(3.3V_2) J8.A12(3.3V_3) J8.A14(3.3V_4) J8.A16(3.3V_5) J8.A18(3.3V_6) J8.A70(3.3V_7) J8.A72(3.3V_8) J8.A74(3.3V_9) R2786.2 R2843.1 R3716.1 R3718.1 R4126.1 R4127.1 R4269.2
P3V3_M2I: R3708.2 R3709.1 U82.D1(BUS) ; also on sheet 41
P3V3_M2I_L: C206.1 C207.1 C208.1 C209.1 C210.1 C211.1 C212.1 C213.1 C214.1 J34.B2(3.3V_10) J34.B4(3.3V_11) J34.B12(3.3V_12) J34.B14(3.3V_13) J34.B16(3.3V_14) J34.B18(3.3V_15) J34.B70(3.3V_16) J34.B72(3.3V_17) J34.B74(3.3V_18) R2888.2 R2889.1 R3708.1 R3710.1 R4130.1 R4131.1 R4270.2
P3V3_M2J: R3701.2 R3702.1 U81.D1(BUS) ; also on sheet 41
P3V3_M2J_L: C197.1 C198.1 C199.1 C200.1 C201.1 C202.1 C203.1 C204.1 C205.1 J34.A2(3.3V_1) J34.A4(3.3V_2) J34.A12(3.3V_3) J34.A14(3.3V_4) J34.A16(3.3V_5) J34.A18(3.3V_6) J34.A70(3.3V_7) J34.A72(3.3V_8) J34.A74(3.3V_9) R2885.2 R2886.1 R3701.1 R3703.1 R4134.1 R4135.1 R4271.2
P3V3_M2K: R3694.2 R3695.1 U80.D1(BUS) ; also on sheet 41
P3V3_M2K_L: C24.1 C27.1 C94.1 C170.1 C171.1 C172.1 C173.1 C174.1 C175.1 J6.B2(3.3V_10) J6.B4(3.3V_11) J6.B12(3.3V_12) J6.B14(3.3V_13) J6.B16(3.3V_14) J6.B18(3.3V_15) J6.B70(3.3V_16) J6.B72(3.3V_17) J6.B74(3.3V_18) R2783.2 R2842.1 R3694.1 R3696.1 R4138.1 R4139.1 R4272.2
P3V3_STBY: C1099.1 C1101.1 C1103.1 C1105.1 C1107.1 R3697.1 R3698.1 R3704.1 R3705.1 R3711.1 R3712.1 R3719.1 R3720.1 R3726.1 R3727.1 R3890.2 R3891.2 R3892.2 R3893.2 R3894.2 U80.B1(VS) U81.B1(VS) U82.B1(VS) U83.B1(VS) U84.B1(VS) ; also on sheet 12 17 18 19 20 22 23 24 25 26 27 28 29 35 36 37 38 39 40 41 42 43 44 45 46 47 48 49 50 52 53 54 55 56 57 58 61 67
CLK_100M_DB1200_M2G_R_DN: J8.B53(NC25) ; also on sheet 21
CLK_100M_DB1200_M2G_R_DP: J8.B55(NC26) ; also on sheet 21
CLK_100M_DB1200_M2H_R_DN: J8.A53(REFCLKN) ; also on sheet 21
CLK_100M_DB1200_M2H_R_DP: J8.A55(REFCLKP) ; also on sheet 21
CLK_100M_DB1200_M2I_R_DN: J34.B53(NC25) ; also on sheet 21
CLK_100M_DB1200_M2I_R_DP: J34.B55(NC26) ; also on sheet 21
CLK_100M_DB1200_M2J_R_DN: J34.A53(REFCLKN) ; also on sheet 21
CLK_100M_DB1200_M2J_R_DP: J34.A55(REFCLKP) ; also on sheet 21
CLK_100M_DB1200_M2K_R_DN: J6.B53(NC25) ; also on sheet 21
CLK_100M_DB1200_M2K_R_DP: J6.B55(NC26) ; also on sheet 21
COM_CPLD_M2G_RX: J8.B46(NC17) ; also on sheet 52
COM_CPLD_M2G_TX: R4300.1 ; also on sheet 52
COM_CPLD_M2G_TX_R: J8.B48(NC18) R4300.2
COM_CPLD_M2H_RX: J8.A46(UART_RX) ; also on sheet 52
COM_CPLD_M2H_TX: R4301.1 ; also on sheet 52
COM_CPLD_M2H_TX_R: J8.A48(UART_TX) R4301.2
COM_CPLD_M2I_RX: J34.B46(NC17) ; also on sheet 52
COM_CPLD_M2I_TX: R4302.1 ; also on sheet 52
COM_CPLD_M2I_TX_R: J34.B48(NC18) R4302.2
COM_CPLD_M2J_RX: J34.A46(UART_RX) ; also on sheet 52
COM_CPLD_M2J_TX: R4303.1 ; also on sheet 52
COM_CPLD_M2J_TX_R: J34.A48(UART_TX) R4303.2
COM_CPLD_M2K_RX: J6.B46(NC17) ; also on sheet 52
COM_CPLD_M2K_TX: R4304.1 ; also on sheet 52
COM_CPLD_M2K_TX_R: J6.B48(NC18) R4304.2
JTAG_CPLD_M2G_TCK: J8.B28(GND17) ; also on sheet 51
JTAG_CPLD_M2G_TDI: J8.B24(NC7) ; also on sheet 51
JTAG_CPLD_M2G_TDO: J8.B26(NC8) ; also on sheet 51
JTAG_CPLD_M2G_TMS: J8.B67(NC27) ; also on sheet 51
JTAG_CPLD_M2G_TRST: J8.B20(NC6) ; also on sheet 51
JTAG_CPLD_M2H_TCK: J8.A28(TCK) ; also on sheet 51
JTAG_CPLD_M2H_TDI: J8.A24(TDI) ; also on sheet 51
JTAG_CPLD_M2H_TDO: J8.A26(TDO) ; also on sheet 51
JTAG_CPLD_M2H_TMS: J8.A67(TMS) ; also on sheet 51
JTAG_CPLD_M2H_TRST: J8.A20(TRST) ; also on sheet 51
JTAG_CPLD_M2I_TCK: J34.B28(GND17) ; also on sheet 51
JTAG_CPLD_M2I_TDI: J34.B24(NC7) ; also on sheet 51
JTAG_CPLD_M2I_TDO: J34.B26(NC8) ; also on sheet 51
JTAG_CPLD_M2I_TMS: J34.B67(NC27) ; also on sheet 51
JTAG_CPLD_M2I_TRST: J34.B20(NC6) ; also on sheet 51
JTAG_CPLD_M2J_TCK: J34.A28(TCK) ; also on sheet 51
JTAG_CPLD_M2J_TDI: J34.A24(TDI) ; also on sheet 51
JTAG_CPLD_M2J_TDO: J34.A26(TDO) ; also on sheet 51
JTAG_CPLD_M2J_TMS: J34.A67(TMS) ; also on sheet 51
JTAG_CPLD_M2J_TRST: J34.A20(TRST) ; also on sheet 51
JTAG_CPLD_M2K_TCK: J6.B28(GND17) ; also on sheet 51
JTAG_CPLD_M2K_TDI: J6.B24(NC7) ; also on sheet 51
JTAG_CPLD_M2K_TDO: J6.B26(NC8) ; also on sheet 51
JTAG_CPLD_M2K_TMS: J6.B67(NC27) ; also on sheet 51
JTAG_CPLD_M2K_TRST: J6.B20(NC6) ; also on sheet 51
M2G_LED: J8.B10(NC5) R2844.2
M2G_VIO_CFG: J8.B73(GND30) R4247.2
M2H_LED: J8.A10(LED_1#) R2843.2
M2H_VIO_CFG: J8.A73(VIO_CFG_GND) R4249.2
M2I_LED: J34.B10(NC5) R2889.2
M2I_VIO_CFG: J34.B73(GND30) R4251.2
M2J_LED: J34.A10(LED_1#) R2886.2
M2J_VIO_CFG: J34.A73(VIO_CFG_GND) R4253.2
M2K_LED: J6.B10(NC5) R2842.2
M2K_VIO_CFG: J6.B73(GND30) R4255.2
P3E_PESW_M2G_RX0_DN: J8.B41(PERN4) ; also on sheet 14
P3E_PESW_M2G_RX0_DP: J8.B43(PERP4) ; also on sheet 14
P3E_PESW_M2G_RX1_DN: J8.B29(PERN5) ; also on sheet 14
P3E_PESW_M2G_RX1_DP: J8.B31(PERP5) ; also on sheet 14
P3E_PESW_M2G_RX2_DN: J8.B17(PERN6) ; also on sheet 14
P3E_PESW_M2G_RX2_DP: J8.B19(PERP6) ; also on sheet 14
P3E_PESW_M2G_RX3_DN: J8.B5(PERN7) ; also on sheet 14
P3E_PESW_M2G_RX3_DP: J8.B7(PERP7) ; also on sheet 14
P3E_PESW_M2G_TX0_C_DN: J8.B47(PETN4) ; also on sheet 14
P3E_PESW_M2G_TX0_C_DP: J8.B49(PETP4) ; also on sheet 14
P3E_PESW_M2G_TX1_C_DN: J8.B35(PETN5) ; also on sheet 14
P3E_PESW_M2G_TX1_C_DP: J8.B37(PETP5) ; also on sheet 14
P3E_PESW_M2G_TX2_C_DN: J8.B23(PETN6) ; also on sheet 14
P3E_PESW_M2G_TX2_C_DP: J8.B25(PETP6) ; also on sheet 14
P3E_PESW_M2G_TX3_C_DN: J8.B11(PETN7) ; also on sheet 14
P3E_PESW_M2G_TX3_C_DP: J8.B13(PETP7) ; also on sheet 14
P3E_PESW_M2H_RX0_DN: J8.A41(PERN0) ; also on sheet 14
P3E_PESW_M2H_RX0_DP: J8.A43(PERP0) ; also on sheet 14
P3E_PESW_M2H_RX1_DN: J8.A29(PERN1) ; also on sheet 14
P3E_PESW_M2H_RX1_DP: J8.A31(PERP1) ; also on sheet 14
P3E_PESW_M2H_RX2_DN: J8.A17(PERN2) ; also on sheet 14
P3E_PESW_M2H_RX2_DP: J8.A19(PERP2) ; also on sheet 14
P3E_PESW_M2H_RX3_DN: J8.A5(PERN3) ; also on sheet 14
P3E_PESW_M2H_RX3_DP: J8.A7(PERP3) ; also on sheet 14
P3E_PESW_M2H_TX0_C_DN: J8.A47(PETN0) ; also on sheet 14
P3E_PESW_M2H_TX0_C_DP: J8.A49(PETP0) ; also on sheet 14
P3E_PESW_M2H_TX1_C_DN: J8.A35(PETN1) ; also on sheet 14
P3E_PESW_M2H_TX1_C_DP: J8.A37(PETP1) ; also on sheet 14
P3E_PESW_M2H_TX2_C_DN: J8.A23(PETN2) ; also on sheet 14
P3E_PESW_M2H_TX2_C_DP: J8.A25(PETP2) ; also on sheet 14
P3E_PESW_M2H_TX3_C_DN: J8.A11(PETN3) ; also on sheet 14
P3E_PESW_M2H_TX3_C_DP: J8.A13(PETP3) ; also on sheet 14
P3E_PESW_M2I_RX0_DN: J34.B41(PERN4) ; also on sheet 14
P3E_PESW_M2I_RX0_DP: J34.B43(PERP4) ; also on sheet 14
P3E_PESW_M2I_RX1_DN: J34.B29(PERN5) ; also on sheet 14
P3E_PESW_M2I_RX1_DP: J34.B31(PERP5) ; also on sheet 14
P3E_PESW_M2I_RX2_DN: J34.B17(PERN6) ; also on sheet 14
P3E_PESW_M2I_RX2_DP: J34.B19(PERP6) ; also on sheet 14
P3E_PESW_M2I_RX3_DN: J34.B5(PERN7) ; also on sheet 14
P3E_PESW_M2I_RX3_DP: J34.B7(PERP7) ; also on sheet 14
P3E_PESW_M2I_TX0_C_DN: J34.B47(PETN4) ; also on sheet 14
P3E_PESW_M2I_TX0_C_DP: J34.B49(PETP4) ; also on sheet 14
P3E_PESW_M2I_TX1_C_DN: J34.B35(PETN5) ; also on sheet 14
P3E_PESW_M2I_TX1_C_DP: J34.B37(PETP5) ; also on sheet 14
P3E_PESW_M2I_TX2_C_DN: J34.B23(PETN6) ; also on sheet 14
P3E_PESW_M2I_TX2_C_DP: J34.B25(PETP6) ; also on sheet 14
P3E_PESW_M2I_TX3_C_DN: J34.B11(PETN7) ; also on sheet 14
P3E_PESW_M2I_TX3_C_DP: J34.B13(PETP7) ; also on sheet 14
P3E_PESW_M2J_RX0_DN: J34.A41(PERN0) ; also on sheet 14
P3E_PESW_M2J_RX0_DP: J34.A43(PERP0) ; also on sheet 14
P3E_PESW_M2J_RX1_DN: J34.A29(PERN1) ; also on sheet 14
P3E_PESW_M2J_RX1_DP: J34.A31(PERP1) ; also on sheet 14
P3E_PESW_M2J_RX2_DN: J34.A17(PERN2) ; also on sheet 14
P3E_PESW_M2J_RX2_DP: J34.A19(PERP2) ; also on sheet 14
P3E_PESW_M2J_RX3_DN: J34.A5(PERN3) ; also on sheet 14
P3E_PESW_M2J_RX3_DP: J34.A7(PERP3) ; also on sheet 14
P3E_PESW_M2J_TX0_C_DN: J34.A47(PETN0) ; also on sheet 14
P3E_PESW_M2J_TX0_C_DP: J34.A49(PETP0) ; also on sheet 14
P3E_PESW_M2J_TX1_C_DN: J34.A35(PETN1) ; also on sheet 14
P3E_PESW_M2J_TX1_C_DP: J34.A37(PETP1) ; also on sheet 14
P3E_PESW_M2J_TX2_C_DN: J34.A23(PETN2) ; also on sheet 14
P3E_PESW_M2J_TX2_C_DP: J34.A25(PETP2) ; also on sheet 14
P3E_PESW_M2J_TX3_C_DN: J34.A11(PETN3) ; also on sheet 14
P3E_PESW_M2J_TX3_C_DP: J34.A13(PETP3) ; also on sheet 14
P3E_PESW_M2K_RX0_DN: J6.B41(PERN4) ; also on sheet 15
P3E_PESW_M2K_RX0_DP: J6.B43(PERP4) ; also on sheet 15
P3E_PESW_M2K_RX1_DN: J6.B29(PERN5) ; also on sheet 15
P3E_PESW_M2K_RX1_DP: J6.B31(PERP5) ; also on sheet 15
P3E_PESW_M2K_RX2_DN: J6.B17(PERN6) ; also on sheet 15
P3E_PESW_M2K_RX2_DP: J6.B19(PERP6) ; also on sheet 15
P3E_PESW_M2K_RX3_DN: J6.B5(PERN7) ; also on sheet 15
P3E_PESW_M2K_RX3_DP: J6.B7(PERP7) ; also on sheet 15
P3E_PESW_M2K_TX0_C_DN: J6.B47(PETN4) ; also on sheet 15
P3E_PESW_M2K_TX0_C_DP: J6.B49(PETP4) ; also on sheet 15
P3E_PESW_M2K_TX1_C_DN: J6.B35(PETN5) ; also on sheet 15
P3E_PESW_M2K_TX1_C_DP: J6.B37(PETP5) ; also on sheet 15
P3E_PESW_M2K_TX2_C_DN: J6.B23(PETN6) ; also on sheet 15
P3E_PESW_M2K_TX2_C_DP: J6.B25(PETP6) ; also on sheet 15
P3E_PESW_M2K_TX3_C_DN: J6.B11(PETN7) ; also on sheet 15
P3E_PESW_M2K_TX3_C_DP: J6.B13(PETP7) ; also on sheet 15
PD_M2G_PWRDIS: J8.B6(NC3) R4123.2 R4124.1
PD_M2H_PWRDIS: J8.A6(PWRDIS) R4127.2 R4128.1
PD_M2I_PWRDIS: J34.B6(NC3) R4131.2 R4132.1
PD_M2J_PWRDIS: J34.A6(PWRDIS) R4135.2 R4136.1
PD_M2K_PWRDIS: J6.B6(NC3) R4139.2 R4140.1
PU_INA231_M2G_A0: R3726.2 U84.B3(A0)
PU_INA231_M2G_A1: R3727.2 U84.C3(A1)
PU_INA231_M2H_A0: R3719.2 U83.B3(A0)
PU_INA231_M2H_A1: R3720.2 U83.C3(A1)
PU_INA231_M2I_A0: R3711.2 U82.B3(A0)
PU_INA231_M2I_A1: R3712.2 U82.C3(A1)
PU_INA231_M2J_A0: R3704.2 U81.B3(A0)
PU_INA231_M2J_A1: R3705.2 U81.C3(A1)
PU_INA231_M2K_A0: R3697.2 U80.B3(A0)
PU_INA231_M2K_A1: R3698.2 U80.C3(A1)
PU_M2G_CLKREQ_N: J8.B52(NC20) R2789.1
PU_M2G_PLA_S3_N: J8.B30(NC9) R4268.1
PU_M2G_VIO_1V8: J8.B22(GND16) R4246.2
PU_M2H_CLKREQ_N: J8.A52(CLKREQ#) R2786.1
PU_M2H_PLA_S3_N: J8.A30(PLA_S3#) R4269.1
PU_M2H_VIO_1V8: J8.A22(VIO_1V8) R4248.2
PU_M2I_CLKREQ_N: J34.B52(NC20) R2888.1
PU_M2I_PLA_S3_N: J34.B30(NC9) R4270.1
PU_M2I_VIO_1V8: J34.B22(GND16) R4250.2
PU_M2J_CLKREQ_N: J34.A52(CLKREQ#) R2885.1
PU_M2J_VIO_1V8: J34.A22(VIO_1V8) R4252.2
PU_M2K_CLKREQ_N: J6.B52(NC20) R2783.1
PU_M2K_PLA_S3_N: J6.B30(NC9) R4272.1
PU_M2K_VIO_1V8: J6.B22(GND16) R4254.2
RESERVED_M2G_PLN_N: J8.B8(NC4) R4122.2 R4125.1
RESERVED_M2H_PLN_N: J8.A8(PLN#) R4126.2 R4129.1
RESERVED_M2I_PLN_N: J34.B8(NC4) R4130.2 R4133.1
RESERVED_M2J_PLN_N: J34.A8(PLN#) R4134.2 R4137.1
RESERVED_M2K_PLN_N: J6.B8(NC4) R4138.2 R4141.1
RST_PESW_M2G_LVC_N: J8.B50(NC19) ; also on sheet 44
RST_PESW_M2H_LVC_N: J8.A50(PERST#) ; also on sheet 44
RST_PESW_M2I_LVC_N: J34.B50(NC19) ; also on sheet 44
RST_PESW_M2J_LVC_N: J34.A50(PERST#) ; also on sheet 44
RST_PESW_M2K_LVC_N: J6.B50(NC19) ; also on sheet 44
SMB_M2G_ALERT_N: J8.B44(NC16) ; also on sheet 49
SMB_M2G_INA231_ALRT_N: R4027.2 ; also on sheet 46
SMB_M2G_INA231_ALRT_N_R: R3894.1 R4027.1 U84.A3(ALERT)
SMB_M2G_INA231_CLK_R1: R3721.1 U84.A1(SCL)
SMB_M2G_INA231_DAT_R1: R3722.1 U84.A2(SDA)
SMB_M2G_P1V8_CLK: J8.B40(NC14) R3721.2 ; also on sheet 37
SMB_M2G_P1V8_DAT: J8.B42(NC15) R3722.2 ; also on sheet 37
SMB_M2H_ALERT_N: J8.A44(ALERT#) ; also on sheet 49
SMB_M2H_INA231_ALRT_N: R4026.2 ; also on sheet 46
SMB_M2H_INA231_ALRT_N_R: R3893.1 R4026.1 U83.A3(ALERT)
SMB_M2H_INA231_CLK_R1: R3714.1 U83.A1(SCL)
SMB_M2H_INA231_DAT_R1: R3715.1 U83.A2(SDA)
SMB_M2H_P1V8_CLK: J8.A40(SMB_CLK) R3714.2 ; also on sheet 37
SMB_M2H_P1V8_DAT: J8.A42(SMB_DATA) R3715.2 ; also on sheet 37
SMB_M2I_ALERT_N: J34.B44(NC16) ; also on sheet 49
SMB_M2I_INA231_ALRT_N: R4025.2 ; also on sheet 46
SMB_M2I_INA231_ALRT_N_R: R3892.1 R4025.1 U82.A3(ALERT)
SMB_M2I_INA231_CLK_R1: R3706.1 U82.A1(SCL)
SMB_M2I_INA231_DAT_R1: R3707.1 U82.A2(SDA)
SMB_M2I_P1V8_CLK: J34.B40(NC14) R3706.2 ; also on sheet 37
SMB_M2I_P1V8_DAT: J34.B42(NC15) R3707.2 ; also on sheet 37
SMB_M2J_ALERT_N: J34.A44(ALERT#) ; also on sheet 49
SMB_M2J_INA231_ALRT_N: R4024.2 ; also on sheet 46
SMB_M2J_INA231_ALRT_N_R: R3891.1 R4024.1 U81.A3(ALERT)
SMB_M2J_INA231_CLK_R1: R3699.1 U81.A1(SCL)
SMB_M2J_INA231_DAT_R1: R3700.1 U81.A2(SDA)
SMB_M2J_P1V8_CLK: J34.A40(SMB_CLK) R3699.2 ; also on sheet 37
SMB_M2J_P1V8_DAT: J34.A42(SMB_DATA) R3700.2 ; also on sheet 37
SMB_M2K_ALERT_N: J6.B44(NC16) ; also on sheet 49
SMB_M2K_INA231_ALRT_N: R4023.2 ; also on sheet 46
SMB_M2K_INA231_ALRT_N_R: R3890.1 R4023.1 U80.A3(ALERT)
SMB_M2K_INA231_CLK_R1: R3692.1 U80.A1(SCL)
SMB_M2K_INA231_DAT_R1: R3693.1 U80.A2(SDA)
SMB_M2K_P1V8_CLK: J6.B40(NC14) R3692.2 ; also on sheet 37
SMB_M2K_P1V8_DAT: J6.B42(NC15) R3693.2 ; also on sheet 37
TP_M2G_MFG_CLK: J8.B58(NC23) TP12.1
TP_M2G_MFG_DAT: J8.B56(NC22) TP11.1
TP_M2H_MFG_CLK: J8.A58(MFG_CLK) TP10.1
TP_M2H_MFG_DAT: J8.A56(MFG_DATA) TP9.1
TP_M2I_MFG_CLK: J34.B58(NC23) TP16.1
TP_M2I_MFG_DAT: J34.B56(NC22) TP15.1
TP_M2J_MFG_CLK: J34.A58(MFG_CLK) TP14.1
TP_M2J_MFG_DAT: J34.A56(MFG_DATA) TP13.1
TP_M2J_PLA_S3_N: J34.A30(PLA_S3#) R4271.1
TP_M2K_MFG_CLK: J6.B58(NC23) TP8.1
TP_M2K_MFG_DAT: J6.B56(NC22) TP7.1
TP_PEWAKE_M2G: J8.B54(NC21) TP60.1
TP_PEWAKE_M2H: J8.A54(PEWAKE#) TP59.1
TP_PEWAKE_M2I: J34.B54(NC21) TP58.1
TP_PEWAKE_M2J: J34.A54(PEWAKE#) TP57.1
TP_PEWAKE_M2K: J6.B54(NC21) TP56.1
TP_USB2_M2G_DN: J8.B36(NC12) TP48.1
TP_USB2_M2G_DP: J8.B34(NC11) TP47.1
TP_USB2_M2H_DN: J8.A36(USB_D-) TP46.1
TP_USB2_M2H_DP: J8.A34(USB_D+) TP45.1
TP_USB2_M2I_DN: J34.B36(NC12) TP44.1
TP_USB2_M2I_DP: J34.B34(NC11) TP43.1
TP_USB2_M2J_DN: J34.A36(USB_D-) TP42.1
TP_USB2_M2J_DP: J34.A34(USB_D+) TP41.1
TP_USB2_M2K_DN: J6.B36(NC12) TP40.1
TP_USB2_M2K_DP: J6.B34(NC11) TP39.1
VSENSE_P3V3_M2G_INA231_INN: C1108.2 R3725.2 U84.D2(IN-)
VSENSE_P3V3_M2G_INA231_INP: C1108.1 R3724.2 U84.D3(IN+)
VSENSE_P3V3_M2H_INA231_INN: C1106.2 R3718.2 U83.D2(IN-)
VSENSE_P3V3_M2H_INA231_INP: C1106.1 R3717.2 U83.D3(IN+)
VSENSE_P3V3_M2I_INA231_INN: C1104.2 R3710.2 U82.D2(IN-)
VSENSE_P3V3_M2I_INA231_INP: C1104.1 R3709.2 U82.D3(IN+)
VSENSE_P3V3_M2J_INA231_INN: C1102.2 R3703.2 U81.D2(IN-)
VSENSE_P3V3_M2J_INA231_INP: C1102.1 R3702.2 U81.D3(IN+)
VSENSE_P3V3_M2K_INA231_INN: C1100.2 R3696.2 U80.D2(IN-)
VSENSE_P3V3_M2K_INA231_INP: C1100.1 R3695.2 U80.D3(IN+)

Not connected (* = marked no-connect by the designer): J6 B68(NC24) B69(NC28); J8 A68(NC1) A69(NC2) B68(NC24) B69(NC28); J34 A68(NC1) A69(NC2) B68(NC24) B69(NC28); U80 B2(NC)* C2(NC)*; U81 B2(NC)* C2(NC)*; U82 B2(NC)* C2(NC)*; U83 B2(NC)* C2(NC)*; U84 B2(NC)* C2(NC)*

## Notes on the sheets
sheet 30
- CAD Note:
  J8 is dual M.2 connector.
- SMBus (8-Bit) Address:0x8A
- M.2_G
sheet 31
- CAD Note:
  J8 is dual M.2 connector.
- SMBus (8-Bit) Address:0x8A
- M.2_H
sheet 32
- CAD Note:
  J34 is dual M.2 connector.
- SMBus (8-Bit) Address:0x8A
- M.2_I
sheet 33
- CAD Note:
  J34 is dual M.2 connector.
- SMBus (8-Bit) Address:0x8A
- M.2_J
sheet 34
- CAD Note:
  J6 is dual M.2 connector.
- SMBus (8-Bit) Address:0x8A
- M.2_K
